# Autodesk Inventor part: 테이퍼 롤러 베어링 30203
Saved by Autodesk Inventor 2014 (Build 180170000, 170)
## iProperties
Created: 2026-07
Part Number: 테이퍼 롤러 베어링 30203
Material: 강철, 연강
Document SubType Name: Modeling
Designer: dg
Density: 7.86 g/cm^3
Appearance: 강철
Mass: 61.8713 g
Surface Area: 65.104 cm^2
Volume: 7.87166 cm^3
Author: jhkim
Description: 테이퍼 롤러 베어링
Creation Date: 2026-07-02
Sending System: Autodesk Inventor 2027
Preprocessor: ST-DEVELOPER v20.1
Author: dg
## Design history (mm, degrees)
node "테이퍼 롤러 베어링 302031"
body "Solid1"
node "Solid1_1"
node "기준1"
node "기준2"
